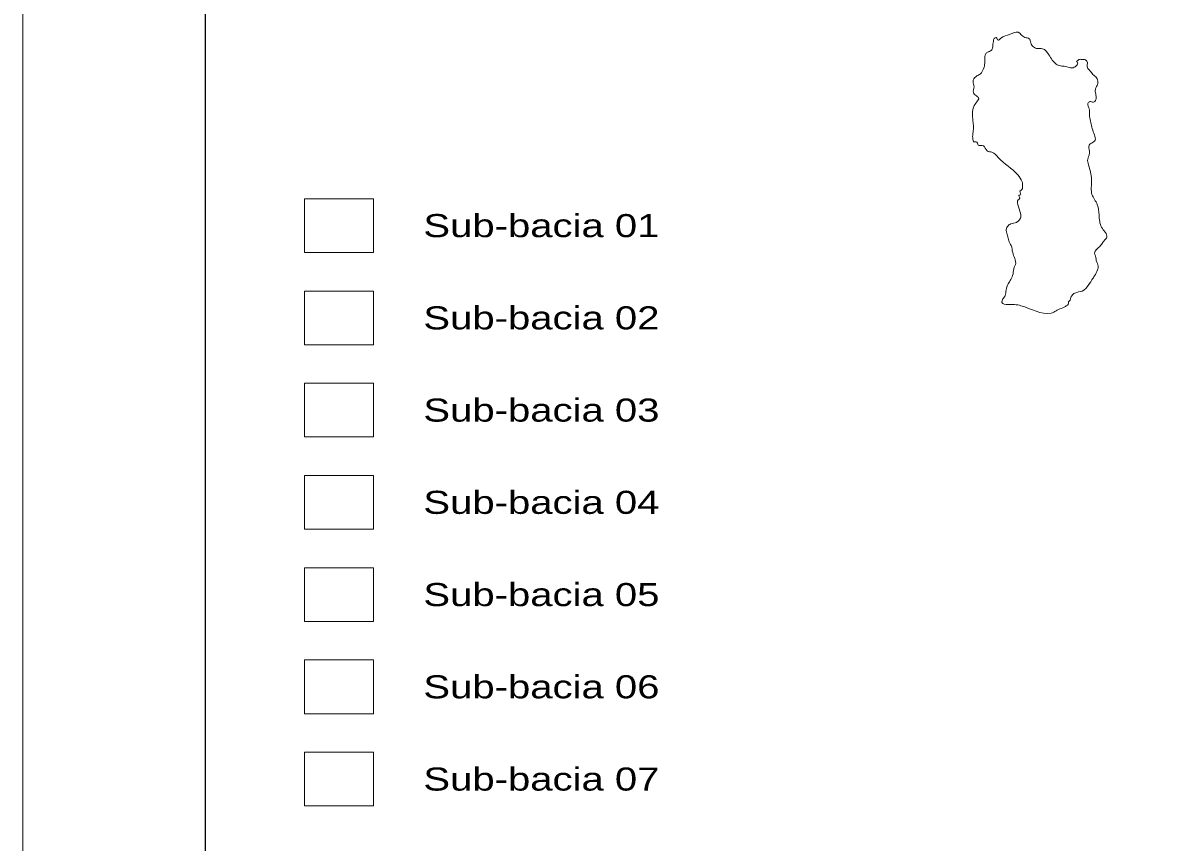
# Model space of a CAD drawing. Extents: x 854879 to 917879, y 8541948 to 8631048.
# Drawn here: x 854879 to 879557, y 8571397 to 8589165 of the extents above; entities that cross this region are included whole.
import ezdxf

# ---------------------------------------------------------------- set-up
doc = ezdxf.new("R2010")
doc.units = 0
doc.header["$LTSCALE"] = 160
for name, color, linetype, lineweight in [('1', 7, 'Continuous', 13), ('18', 7, 'Continuous', 13), ('26', 7, 'Continuous', 13), ('3', 7, 'Continuous', 13), ('36', 7, 'Continuous', 13), ('44', 7, 'Continuous', 13)]:
    doc.layers.add(name, color=color, linetype=linetype, lineweight=lineweight)

msp = doc.modelspace()

# ---------------------------------------------------------------- linework, layer by layer
at = {"layer": '1'}
msp.add_lwpolyline([(916445.6, 8586427.1), (916445.6, 8544954.2), (858846.4, 8544954.2), (858846.4, 8599885.6)], dxfattribs=at)
at = {"layer": '18'}
msp.add_line((877846.1, 8588369.1), (877858.6, 8588369.4), dxfattribs=at)
for points in [[(877858.6, 8588369.4), (877792.5, 8588367.9), (877766.7, 8588347.9), (877740.8, 8588317.8), (877758.5, 8588312.4), (877760.4, 8588276.7), (877713.5, 8588211.2), (877611.3, 8588187.3), (877502.6, 8588217.1), (877391, 8588231.7), (877300.1, 8588268.9), (877141, 8588470.3), (877003.5, 8588600), (876874, 8588607.2), (876786, 8588659.6), (876742, 8588757.2), (876715.1, 8588818.8), (876619, 8588848.4), (876473.6, 8588960.4), (876297.4, 8588914.8), (876092.3, 8588821.3), (876038.3, 8588786.5), (875996.1, 8588843.3), (875955.1, 8588826.1), (875936.2, 8588760.1), (875927.4, 8588699.1), (875910.3, 8588594.8), (875853.5, 8588544.8), (875794.6, 8588517.7), (875760.7, 8588469.8), (875749.9, 8588296.6), (875722.2, 8588167.1), (875654.2, 8588058.5), (875579.7, 8588013.9), (875499.1, 8587918.3), (875505.3, 8587839.2), (875516.9, 8587775.2), (875502, 8587653.1), (875569.3, 8587578.1), (875616.8, 8587534), (875577.2, 8587447.9), (875509.3, 8587349.6), (875493.7, 8587044), (875499.8, 8586814.4), (875488, 8586725.4), (875498.6, 8586607.9), (875510.9, 8586582.2), (875564.3, 8586583.9), (875608.8, 8586514.4), (875659.4, 8586503.3), (875720.3, 8586497.3), (875799.8, 8586388.9), (875906, 8586356.6), (876043.7, 8586242.2), (876464.1, 8585868.2), (876558, 8585716.3), (876568.6, 8585598.8), (876552.5, 8585548.1), (876513.7, 8585510.5), (876528.1, 8585464.4), (876525, 8585433.8), (876491.8, 8585424.2), (876511.1, 8585365.2), (876474.7, 8585322.5), (876467.9, 8585225.7), (876525.5, 8585033.6), (876534.5, 8584967.2), (876500.1, 8584891.2), (876435.5, 8584836.2), (876315.4, 8584802.5), (876240.7, 8584747.6), (876213.8, 8584661.4), (876244.8, 8584548.7), (876270.8, 8584438.7), (876322.3, 8584333.3), (876355.2, 8584182.3), (876401.2, 8584054.1), (876416.7, 8583923.9), (876390.3, 8583868.2), (876362.2, 8583718.2), (876316.8, 8583599.2), (876256.6, 8583503.3), (876213.6, 8583371.4), (876191.2, 8583251.9), (876144, 8583176.2), (876122.3, 8583100.1), (876253.8, 8583057.2), (876396.1, 8583054.9), (876535.4, 8583029.7), (877188.5, 8582871.2), (877247.2, 8582888.1)], [(877247.2, 8582888.1), (877347.4, 8582945.1), (877470.4, 8582999.2), (877532, 8583033.8), (877557.8, 8583053.8), (877566.5, 8583112.3), (877600.2, 8583150), (877619, 8583205.8), (877666.1, 8583281.5), (877745.6, 8583318.5), (877896.4, 8583364.4), (877966.2, 8583432.1), (878075.8, 8583588.4), (878133.3, 8583679.3), (878196.6, 8583805.7), (878210.8, 8583889.6), (878169.7, 8584007.5), (878158.3, 8584084.2), (878148.6, 8584109.8), (878131.9, 8584171.3), (878243.8, 8584317.3), (878311.4, 8584400.4), (878350.5, 8584453.3), (878397.3, 8584511.2), (878363.7, 8584621.3), (878284.3, 8584732.2), (878228.1, 8584998.3), (878191.4, 8585223.2), (878129.8, 8585333.8), (878075.9, 8585444.3), (878060.6, 8585587.3), (878062, 8585809.1), (877991.3, 8586118.7), (877979.7, 8586180.1), (878012.2, 8586291.8), (878018.8, 8586378.3), (878013.6, 8586511), (878106.3, 8586580.8), (878142.6, 8586618.5), (878126.8, 8586733.5), (878047.8, 8587002.4), (878024.7, 8587135.4), (878012.6, 8587308.9), (877989, 8587411.3), (878027.9, 8587456.5), (878106.5, 8587442.5), (878160.8, 8587497.7), (878162.6, 8587597.1), (878146.5, 8587691.7), (878160.3, 8587752.7), (878192, 8587821), (878203.1, 8587874.3), (878174.4, 8587974.2), (878094.3, 8588044.4), (878062.1, 8588088.2), (878014.7, 8588142.5), (877980, 8588189), (877973.6, 8588257.9), (877964.8, 8588334.5), (877932.2, 8588360.6), (877846.1, 8588369.1)]]:
    msp.add_spline(points, degree=3, dxfattribs=at)
at = {"layer": '26'}
for points in [[(860991.4, 8585348.3), (862488.3, 8585348.3), (862488.3, 8584184), (860991.4, 8584184)], [(860991.4, 8583348.3), (862488.3, 8583348.3), (862488.3, 8582184), (860991.4, 8582184)], [(860991.4, 8581348.3), (862488.3, 8581348.3), (862488.3, 8580184), (860991.4, 8580184)], [(860991.4, 8579348.3), (862488.3, 8579348.3), (862488.3, 8578184), (860991.4, 8578184)], [(860991.4, 8577348.3), (862488.3, 8577348.3), (862488.3, 8576184), (860991.4, 8576184)], [(860991.4, 8575348.3), (862488.3, 8575348.3), (862488.3, 8574184), (860991.4, 8574184)], [(860991.4, 8573348.3), (862488.3, 8573348.3), (862488.3, 8572184), (860991.4, 8572184)]]:
    msp.add_lwpolyline(points, close=True, dxfattribs=at)
at = {"layer": '3'}
for points in [[(877858.6, 8588369.4), (877792.5, 8588367.9), (877766.7, 8588347.9), (877740.8, 8588317.8), (877758.5, 8588312.4), (877760.4, 8588276.7), (877713.5, 8588211.2), (877611.3, 8588187.3), (877502.6, 8588217.1), (877391, 8588231.7), (877300.1, 8588268.9), (877141, 8588470.3), (877003.5, 8588600), (876874, 8588607.2), (876786, 8588659.6), (876742, 8588757.2), (876715.1, 8588818.8), (876619, 8588848.4), (876473.6, 8588960.4), (876297.4, 8588914.8), (876092.3, 8588821.3), (876038.3, 8588786.5), (875996.1, 8588843.3), (875955.1, 8588826.1), (875936.2, 8588760.1), (875927.4, 8588699.1), (875910.3, 8588594.8), (875853.5, 8588544.8), (875794.6, 8588517.7), (875760.7, 8588469.8), (875749.9, 8588296.6), (875722.2, 8588167.1), (875654.2, 8588058.5), (875579.7, 8588013.9), (875499.1, 8587918.3), (875505.3, 8587839.2), (875516.9, 8587775.2), (875502, 8587653.1), (875569.3, 8587578.1), (875616.8, 8587534), (875577.2, 8587447.9), (875509.3, 8587349.6), (875493.7, 8587044), (875499.8, 8586814.4), (875488, 8586725.4), (875498.6, 8586607.9), (875510.9, 8586582.2), (875564.3, 8586583.9), (875608.8, 8586514.4), (875659.4, 8586503.3), (875720.3, 8586497.3), (875799.8, 8586388.9), (875906, 8586356.6), (876043.7, 8586242.2), (876464.1, 8585868.2), (876558, 8585716.3), (876568.6, 8585598.8), (876552.5, 8585548.1), (876513.7, 8585510.5), (876528.1, 8585464.4), (876525, 8585433.8), (876491.8, 8585424.2), (876511.1, 8585365.2), (876474.7, 8585322.5), (876467.9, 8585225.7), (876525.5, 8585033.6), (876534.5, 8584967.2), (876500.1, 8584891.2), (876435.5, 8584836.2), (876315.4, 8584802.5), (876240.7, 8584747.6), (876213.8, 8584661.4), (876244.8, 8584548.7), (876270.8, 8584438.7), (876322.3, 8584333.3), (876355.2, 8584182.3), (876401.2, 8584054.1), (876416.7, 8583923.9), (876390.3, 8583868.2), (876362.2, 8583718.2), (876316.8, 8583599.2), (876256.6, 8583503.3), (876213.6, 8583371.4), (876191.2, 8583251.9), (876144, 8583176.2), (876122.3, 8583100.1), (876253.8, 8583057.2), (876396.1, 8583054.9), (876535.4, 8583029.7), (877188.5, 8582871.2), (877247.2, 8582888.1)], [(877247.2, 8582888.1), (877347.4, 8582945.1), (877470.4, 8582999.2), (877532, 8583033.8), (877557.8, 8583053.8), (877566.5, 8583112.3), (877600.2, 8583150), (877619, 8583205.8), (877666.1, 8583281.5), (877745.6, 8583318.5), (877896.4, 8583364.4), (877966.2, 8583432.1), (878075.8, 8583588.4), (878133.3, 8583679.3), (878196.6, 8583805.7), (878210.8, 8583889.6), (878169.7, 8584007.5), (878158.3, 8584084.2), (878148.6, 8584109.8), (878131.9, 8584171.3), (878243.8, 8584317.3), (878311.4, 8584400.4), (878350.5, 8584453.3), (878397.3, 8584511.2), (878363.7, 8584621.3), (878284.3, 8584732.2), (878228.1, 8584998.3), (878191.4, 8585223.2), (878129.8, 8585333.8), (878075.9, 8585444.3), (878060.6, 8585587.3), (878062, 8585809.1), (877991.3, 8586118.7), (877979.7, 8586180.1), (878012.2, 8586291.8), (878018.8, 8586378.3), (878013.6, 8586511), (878106.3, 8586580.8), (878142.6, 8586618.5), (878126.8, 8586733.5), (878047.8, 8587002.4), (878024.7, 8587135.4), (878012.6, 8587308.9), (877989, 8587411.3), (878027.9, 8587456.5), (878106.5, 8587442.5), (878160.8, 8587497.7), (878162.6, 8587597.1), (878146.5, 8587691.7), (878160.3, 8587752.7), (878192, 8587821), (878203.1, 8587874.3), (878174.4, 8587974.2), (878094.3, 8588044.4), (878062.1, 8588088.2), (878014.7, 8588142.5), (877980, 8588189), (877973.6, 8588257.9), (877964.8, 8588334.5), (877932.2, 8588360.6), (877846.1, 8588369.1)]]:
    msp.add_spline(points, degree=3, dxfattribs=at)
at = {"layer": '36'}
msp.add_lwpolyline([(854878.6, 8541948.4), (917878.6, 8541948.4), (917878.6, 8631048.4), (854878.6, 8631048.4)], close=True, dxfattribs=at)
at = {"layer": '36', "lineweight": 25}
msp.add_lwpolyline([(858846.4, 8628560.7), (916445.6, 8628560.7), (916445.6, 8544954.2), (858846.4, 8544954.2)], close=True, dxfattribs=at)
at = {"layer": '44'}
msp.add_lwpolyline([(858846.4, 8628560.7), (916445.6, 8628560.7), (916445.6, 8544954.2), (858846.4, 8544954.2)], close=True, dxfattribs=at)

# ---------------------------------------------------------------- texts
at = {"layer": '26', "width": 1.3}
for s, p in [('Sub-bacia 01', (863569.5, 8584516.7)), ('Sub-bacia 02', (863569.5, 8582516.7)), ('Sub-bacia 03', (863569.5, 8580516.7)), ('Sub-bacia 04', (863569.5, 8578516.7)), ('Sub-bacia 05', (863569.5, 8576516.7)), ('Sub-bacia 06', (863569.5, 8574516.7)), ('Sub-bacia 07', (863569.5, 8572516.7))]:
    msp.add_text(s, height=500, dxfattribs=at).set_placement(p)

doc.saveas('drawing.dxf')
